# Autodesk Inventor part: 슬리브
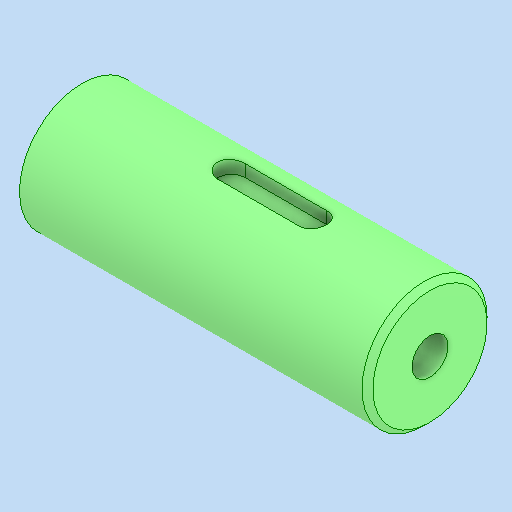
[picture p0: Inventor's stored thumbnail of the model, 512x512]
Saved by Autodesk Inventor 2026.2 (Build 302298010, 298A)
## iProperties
Created: 2026-08
Part Number: 슬리브
Material: 강철, 탄소
Document SubType Name: Modeling
Designer: PC2-02
Density: 7.87 g/cm^3
Appearance: 기본값
Author: jhkim
Sending System: Autodesk Inventor 2027
Preprocessor: ST-DEVELOPER v20.1
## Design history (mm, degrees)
feature "솔리드1"
node "솔리드2"
